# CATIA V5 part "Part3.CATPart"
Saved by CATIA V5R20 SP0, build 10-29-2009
Part number: Part3
Bounding box of the stored display mesh (mm): x 25 to 30, y -4.99 to 144.99, z 60 to 70
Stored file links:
  E:\Ehsan\Amoozesh\CATIA\CATIA Course\Advanced\Exercises\DMU Kinematic\1\Part3.CATPart
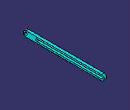
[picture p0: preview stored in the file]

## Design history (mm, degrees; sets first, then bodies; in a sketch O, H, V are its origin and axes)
Body1 (main body)
  DatumSurface1
  DatumCurve1
  Sketch1 on face of DatumSurface1, origin (25, 0, 0), H (0, 1, 0), V (0, 0, 1)
    projected circle E1 centre (0, 65) radius 2.5 from edge of DatumCurve1
    construction line L1 (0, 65) -> (140, 65)
    point P1 (0, 65)
    line L2 (0, 70) -> (140, 70)
    line L3 (140, 60) -> (0, 60)
    arc A1 centre (140, 65) radius 5 from (140, 70) to (140, 60) cw
    arc A2 centre (0, 65) radius 5 from (0, 60) to (0, 70) cw
    construction line L4 (140, 65) -> (20, 65)
    line L5 (140, 63) -> (20, 63)
    line L6 (20, 67) -> (140, 67)
    arc A3 centre (20, 65) radius 2 from (20, 63) to (20, 67) cw
    arc A4 centre (140, 65) radius 2 from (140, 67) to (140, 63) cw
    distance L1 L2 = 5
    length L1 = 140
    distance L4 L5 = 2
    length L4 = 120
    concentricity: P1 E1
    horizontal: L1 H, L4 H
    tangency: A1 L2, A2 L2, A1 L3, A2 L3, A3 L5, A4 L5, A3 L6, A4 L6
  Pad1: profile Sketch1, direction (1, 0, 0), length 5
  Point1: stored without definition
  Line1: type PtDir, RefPoint Point1, Direction edge [end face of Pad1 | face of Pad1 from Sketch1.L5], Start 0, End 20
